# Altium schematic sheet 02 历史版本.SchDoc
size 297 x 209 mm
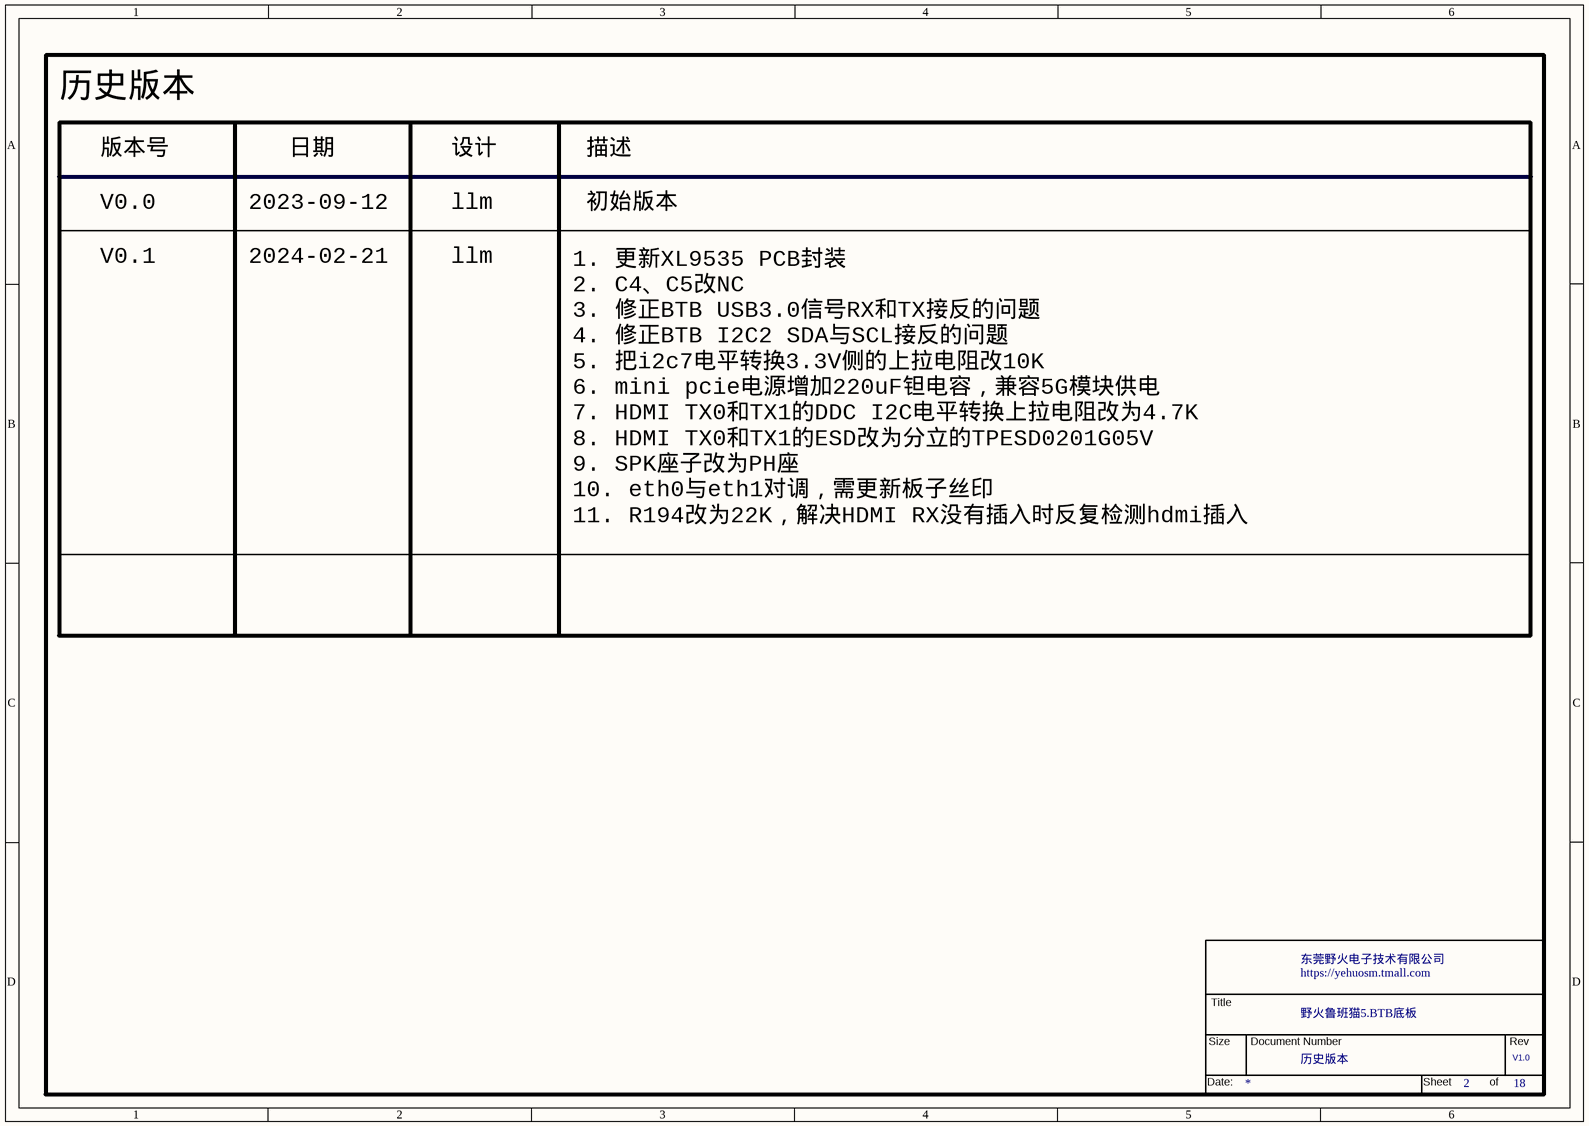
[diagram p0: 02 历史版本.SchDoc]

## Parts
*  Doc: 历史版本  RevCode: V1.0  Title: 野火鲁班猫5.BTB底板  OrgName: 东莞野火电子技术有限公司  Page Number: 2  Page Count: 18  (hidden comment: TitleBlock_YHSCH)  (graphical)

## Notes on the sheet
- 历史版本
- 版本号
- 日期
- 设计
- 描述
- V0.0
- V0.1
- 2023-09-12
- 2024-02-21
- llm
- 1. 更新XL9535 PCB封装
  2. C4、C5改NC
  3. 修正BTB USB3.0信号RX和TX接反的问题
  4. 修正BTB I2C2 SDA与SCL接反的问题
  5. 把i2c7电平转换3.3V侧的上拉电阻改10K
  6. mini pcie电源增加220uF钽电容，兼容5G模块供电
  7. HDMI TX0和TX1的DDC I2C电平转换上拉电阻改为4.7K
  8. HDMI TX0和TX1的ESD改为分立的TPESD0201G05V
  9. SPK座子改为PH座
  10. eth0与eth1对调，需更新板子丝印
  11. R194改为22K，解决HDMI RX没有插入时反复检测hdmi插入
- 初始版本

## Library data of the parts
* = TitleBlock_YHSCH: Cage Code: 1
